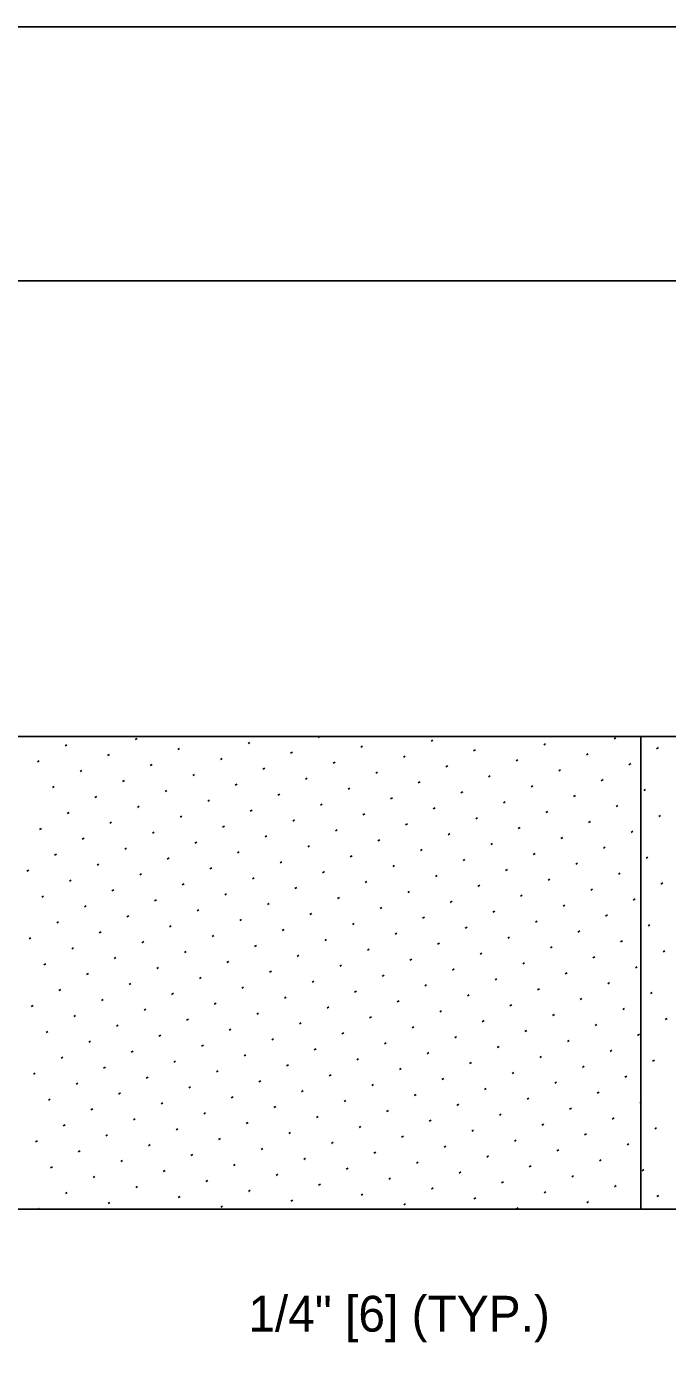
# Model space of a CAD drawing. Extents: x 49991.4 to 50021, y 49987.6 to 50011.4.
# Drawn here: x 50003.6 to 50004.674, y 49996.76 to 49998.999 of the extents above; entities that cross this region are included whole.
import ezdxf

# ---------------------------------------------------------------- set-up
doc = ezdxf.new("R2010")
doc.units = 0
for name, color, linetype in [('Level 1', 7, 'Continuous'), ('Level 2', 7, 'Continuous'), ('Level 3', 7, 'Continuous'), ('Level 6', 7, 'Continuous')]:
    doc.layers.add(name, color=color, linetype=linetype)

msp = doc.modelspace()

# ---------------------------------------------------------------- linework, layer by layer
at = {"layer": 'Level 1'}
for p, q in [((50002.4589, 49997.8102), (50013.6129, 49997.8102)), ((50013.6129, 49997.0183), (50002.4589, 49997.0183))]:
    msp.add_line(p, q, dxfattribs=at)
msp.add_lwpolyline([(49999.3835, 49998.9992), (50016.7501, 49998.9992), (50016.7501, 49987.7988), (49999.3835, 49987.7988)], close=True, dxfattribs=at)
at = {"layer": 'Level 3'}
for p, q in [((50003.6644, 49997.7948), (50003.6674, 49997.7965)), ((50003.7821, 49997.805), (50003.7851, 49997.8067)), ((50003.9711, 49997.7986), (50003.9741, 49997.8004)), ((50004.0887, 49997.8088), (50004.0911, 49997.8102)), ((50004.1601, 49997.7923), (50004.1631, 49997.794)), ((50004.2778, 49997.8025), (50004.2808, 49997.8043)), ((50004.4668, 49997.7962), (50004.4698, 49997.7979)), ((50004.5845, 49997.8064), (50004.5875, 49997.8081)), ((50004.6295, 49997.0183), (50004.6295, 49997.8102)), ((50003.7357, 49997.7782), (50003.7387, 49997.78)), ((50003.8534, 49997.7884), (50003.8564, 49997.7902)), ((50003.9247, 49997.7719), (50003.9278, 49997.7736)), ((50004.0424, 49997.7821), (50004.0454, 49997.7838)), ((50004.2314, 49997.7757), (50004.2345, 49997.7775)), ((50004.3491, 49997.786), (50004.3521, 49997.7877)), ((50004.4204, 49997.7694), (50004.4235, 49997.7712)), ((50004.5381, 49997.7796), (50004.5411, 49997.7814)), ((50004.6558, 49997.7898), (50004.6588, 49997.7916)), ((50003.618, 49997.768), (50003.6211, 49997.7698)), ((50003.6894, 49997.7515), (50003.6924, 49997.7532)), ((50003.8071, 49997.7617), (50003.8101, 49997.7634)), ((50003.9961, 49997.7553), (50003.9991, 49997.7571)), ((50004.1137, 49997.7655), (50004.1168, 49997.7673)), ((50004.1851, 49997.749), (50004.1881, 49997.7507)), ((50004.3028, 49997.7592), (50004.3058, 49997.761)), ((50004.4918, 49997.7529), (50004.4948, 49997.7546)), ((50004.6095, 49997.7631), (50004.6125, 49997.7648)), ((50003.643, 49997.7247), (50003.6461, 49997.7265)), ((50003.7607, 49997.7349), (50003.7637, 49997.7367)), ((50003.8784, 49997.7451), (50003.8814, 49997.7469)), ((50003.9497, 49997.7286), (50003.9528, 49997.7303)), ((50004.0674, 49997.7388), (50004.0704, 49997.7405)), ((50004.2564, 49997.7324), (50004.2595, 49997.7342)), ((50004.3741, 49997.7427), (50004.3771, 49997.7444)), ((50004.4454, 49997.7261), (50004.4485, 49997.7279)), ((50004.5631, 49997.7363), (50004.5661, 49997.7381)), ((50003.7144, 49997.7082), (50003.7174, 49997.7099)), ((50003.8321, 49997.7184), (50003.8351, 49997.7201)), ((50003.9034, 49997.7018), (50003.9064, 49997.7036)), ((50004.0211, 49997.712), (50004.0241, 49997.7138)), ((50004.1387, 49997.7222), (50004.1418, 49997.724)), ((50004.2101, 49997.7057), (50004.2131, 49997.7074)), ((50004.3278, 49997.7159), (50004.3308, 49997.7176)), ((50004.5168, 49997.7096), (50004.5198, 49997.7113)), ((50004.6345, 49997.7198), (50004.6375, 49997.7215)), ((50003.668, 49997.6814), (50003.6711, 49997.6832)), ((50003.7857, 49997.6916), (50003.7887, 49997.6934)), ((50003.9747, 49997.6853), (50003.9778, 49997.687)), ((50004.0924, 49997.6955), (50004.0954, 49997.6972)), ((50004.1637, 49997.6789), (50004.1668, 49997.6807)), ((50004.2814, 49997.6891), (50004.2845, 49997.6909)), ((50004.3991, 49997.6994), (50004.4021, 49997.7011)), ((50004.4704, 49997.6828), (50004.4735, 49997.6846)), ((50004.5881, 49997.693), (50004.5911, 49997.6948)), ((50003.7394, 49997.6649), (50003.7424, 49997.6666)), ((50003.8571, 49997.6751), (50003.8601, 49997.6768)), ((50003.9284, 49997.6585), (50003.9314, 49997.6603)), ((50004.0461, 49997.6687), (50004.0491, 49997.6705)), ((50004.2351, 49997.6624), (50004.2381, 49997.6641)), ((50004.3528, 49997.6726), (50004.3558, 49997.6743)), ((50004.5418, 49997.6663), (50004.5448, 49997.668)), ((50004.6595, 49997.6765), (50004.6625, 49997.6782)), ((50003.6217, 49997.6547), (50003.6247, 49997.6564)), ((50003.693, 49997.6381), (50003.6961, 49997.6399)), ((50003.8107, 49997.6483), (50003.8137, 49997.6501)), ((50003.9997, 49997.642), (50004.0028, 49997.6437)), ((50004.1174, 49997.6522), (50004.1204, 49997.6539)), ((50004.1887, 49997.6356), (50004.1918, 49997.6374)), ((50004.3064, 49997.6458), (50004.3095, 49997.6476)), ((50004.4241, 49997.656), (50004.4271, 49997.6578)), ((50004.4954, 49997.6395), (50004.4985, 49997.6413)), ((50004.6131, 49997.6497), (50004.6161, 49997.6515)), ((50003.7644, 49997.6216), (50003.7674, 49997.6233)), ((50003.8821, 49997.6318), (50003.8851, 49997.6335)), ((50003.9534, 49997.6152), (50003.9564, 49997.617)), ((50004.0711, 49997.6254), (50004.0741, 49997.6272)), ((50004.2601, 49997.6191), (50004.2631, 49997.6208)), ((50004.3778, 49997.6293), (50004.3808, 49997.631)), ((50004.4491, 49997.6127), (50004.4521, 49997.6145)), ((50004.5668, 49997.623), (50004.5698, 49997.6247)), ((50003.6467, 49997.6114), (50003.6497, 49997.6131)), ((50003.718, 49997.5948), (50003.7211, 49997.5966)), ((50003.8357, 49997.605), (50003.8387, 49997.6068)), ((50004.0247, 49997.5987), (50004.0278, 49997.6004)), ((50004.1424, 49997.6089), (50004.1454, 49997.6106)), ((50004.2137, 49997.5923), (50004.2168, 49997.5941)), ((50004.3314, 49997.6025), (50004.3345, 49997.6043)), ((50004.5204, 49997.5962), (50004.5235, 49997.598)), ((50004.6381, 49997.6064), (50004.6411, 49997.6082)), ((50003.6004, 49997.5846), (50003.6034, 49997.5864)), ((50003.6717, 49997.5681), (50003.6747, 49997.5698)), ((50003.7894, 49997.5783), (50003.7924, 49997.58)), ((50003.9071, 49997.5885), (50003.9101, 49997.5902)), ((50003.9784, 49997.5719), (50003.9814, 49997.5737)), ((50004.0961, 49997.5821), (50004.0991, 49997.5839)), ((50004.2851, 49997.5758), (50004.2881, 49997.5775)), ((50004.4028, 49997.586), (50004.4058, 49997.5877)), ((50004.4741, 49997.5694), (50004.4771, 49997.5712)), ((50004.5918, 49997.5797), (50004.5948, 49997.5814)), ((50003.743, 49997.5515), (50003.7461, 49997.5533)), ((50003.8607, 49997.5617), (50003.8637, 49997.5635)), ((50003.9321, 49997.5452), (50003.9351, 49997.5469)), ((50004.0497, 49997.5554), (50004.0528, 49997.5571)), ((50004.1674, 49997.5656), (50004.1704, 49997.5673)), ((50004.2387, 49997.549), (50004.2418, 49997.5508)), ((50004.3564, 49997.5592), (50004.3595, 49997.561)), ((50004.5454, 49997.5529), (50004.5485, 49997.5546)), ((50004.6631, 49997.5631), (50004.6661, 49997.5649)), ((50003.6254, 49997.5413), (50003.6284, 49997.5431)), ((50003.6967, 49997.5248), (50003.6997, 49997.5265)), ((50003.8144, 49997.535), (50003.8174, 49997.5367)), ((50004.0034, 49997.5286), (50004.0064, 49997.5304)), ((50004.1211, 49997.5388), (50004.1241, 49997.5406)), ((50004.1924, 49997.5223), (50004.1954, 49997.524)), ((50004.3101, 49997.5325), (50004.3131, 49997.5342)), ((50004.4278, 49997.5427), (50004.4308, 49997.5444)), ((50004.4991, 49997.5261), (50004.5021, 49997.5279)), ((50004.6168, 49997.5364), (50004.6198, 49997.5381)), ((50003.768, 49997.5082), (50003.7711, 49997.51)), ((50003.8857, 49997.5184), (50003.8887, 49997.5202)), ((50003.9571, 49997.5019), (50003.9601, 49997.5036)), ((50004.0747, 49997.5121), (50004.0778, 49997.5138)), ((50004.2637, 49997.5057), (50004.2668, 49997.5075)), ((50004.3814, 49997.5159), (50004.3845, 49997.5177)), ((50004.5704, 49997.5096), (50004.5735, 49997.5113)), ((50003.6504, 49997.498), (50003.6534, 49997.4998)), ((50003.7217, 49997.4815), (50003.7247, 49997.4832)), ((50003.8394, 49997.4917), (50003.8424, 49997.4934)), ((50004.0284, 49997.4853), (50004.0314, 49997.4871)), ((50004.1461, 49997.4955), (50004.1491, 49997.4973)), ((50004.2174, 49997.479), (50004.2204, 49997.4807)), ((50004.3351, 49997.4892), (50004.3381, 49997.4909)), ((50004.4528, 49997.4994), (50004.4558, 49997.5011)), ((50004.5241, 49997.4828), (50004.5271, 49997.4846)), ((50004.6418, 49997.4931), (50004.6448, 49997.4948)), ((50003.604, 49997.4713), (50003.6071, 49997.473)), ((50003.793, 49997.4649), (50003.7961, 49997.4667)), ((50003.9107, 49997.4751), (50003.9137, 49997.4769)), ((50003.9821, 49997.4586), (50003.9851, 49997.4603)), ((50004.0997, 49997.4688), (50004.1028, 49997.4705)), ((50004.2887, 49997.4624), (50004.2918, 49997.4642)), ((50004.4064, 49997.4726), (50004.4095, 49997.4744)), ((50004.4778, 49997.4561), (50004.4808, 49997.4578)), ((50004.5954, 49997.4663), (50004.5985, 49997.468)), ((50003.6754, 49997.4547), (50003.6784, 49997.4565)), ((50003.7467, 49997.4382), (50003.7497, 49997.4399)), ((50003.8644, 49997.4484), (50003.8674, 49997.4501)), ((50004.0534, 49997.442), (50004.0564, 49997.4438)), ((50004.1711, 49997.4522), (50004.1741, 49997.454)), ((50004.2424, 49997.4357), (50004.2454, 49997.4374)), ((50004.3601, 49997.4459), (50004.3631, 49997.4476)), ((50004.5491, 49997.4395), (50004.5521, 49997.4413)), ((50004.6668, 49997.4497), (50004.6698, 49997.4515)), ((50003.629, 49997.428), (50003.6321, 49997.4297)), ((50003.7004, 49997.4114), (50003.7034, 49997.4132)), ((50003.818, 49997.4216), (50003.8211, 49997.4234)), ((50003.9357, 49997.4318), (50003.9387, 49997.4336)), ((50004.0071, 49997.4153), (50004.0101, 49997.417)), ((50004.1247, 49997.4255), (50004.1278, 49997.4272)), ((50004.3137, 49997.4191), (50004.3168, 49997.4209)), ((50004.4314, 49997.4293), (50004.4345, 49997.4311)), ((50004.5028, 49997.4128), (50004.5058, 49997.4145)), ((50004.6204, 49997.423), (50004.6235, 49997.4247)), ((50003.7717, 49997.3949), (50003.7747, 49997.3966)), ((50003.8894, 49997.4051), (50003.8924, 49997.4068)), ((50003.9607, 49997.3885), (50003.9637, 49997.3903)), ((50004.0784, 49997.3987), (50004.0814, 49997.4005)), ((50004.1961, 49997.4089), (50004.1991, 49997.4107)), ((50004.2674, 49997.3924), (50004.2704, 49997.3941)), ((50004.3851, 49997.4026), (50004.3881, 49997.4043)), ((50004.5741, 49997.3962), (50004.5771, 49997.398)), ((50003.654, 49997.3847), (50003.6571, 49997.3864)), ((50003.7254, 49997.3681), (50003.7284, 49997.3699)), ((50003.843, 49997.3783), (50003.8461, 49997.3801)), ((50004.0321, 49997.372), (50004.0351, 49997.3737)), ((50004.1497, 49997.3822), (50004.1528, 49997.3839)), ((50004.2211, 49997.3656), (50004.2241, 49997.3674)), ((50004.3387, 49997.3758), (50004.3418, 49997.3776)), ((50004.4564, 49997.386), (50004.4595, 49997.3878)), ((50004.5278, 49997.3695), (50004.5308, 49997.3712)), ((50004.6454, 49997.3797), (50004.6485, 49997.3814)), ((50003.6077, 49997.3579), (50003.6107, 49997.3596)), ((50003.7967, 49997.3516), (50003.7997, 49997.3533)), ((50003.9144, 49997.3618), (50003.9174, 49997.3635)), ((50003.9857, 49997.3452), (50003.9887, 49997.347)), ((50004.1034, 49997.3554), (50004.1064, 49997.3572)), ((50004.2924, 49997.3491), (50004.2954, 49997.3508)), ((50004.4101, 49997.3593), (50004.4131, 49997.361)), ((50004.5991, 49997.3529), (50004.6021, 49997.3547)), ((50003.679, 49997.3414), (50003.6821, 49997.3431)), ((50003.7504, 49997.3248), (50003.7534, 49997.3266)), ((50003.868, 49997.335), (50003.8711, 49997.3368)), ((50004.0571, 49997.3287), (50004.0601, 49997.3304)), ((50004.1747, 49997.3389), (50004.1778, 49997.3406)), ((50004.2461, 49997.3223), (50004.2491, 49997.3241)), ((50004.3637, 49997.3325), (50004.3668, 49997.3343)), ((50004.4814, 49997.3427), (50004.4845, 49997.3445)), ((50004.5528, 49997.3262), (50004.5558, 49997.3279)), ((50004.6704, 49997.3364), (50004.6735, 49997.3381)), ((50003.6327, 49997.3146), (50003.6357, 49997.3163)), ((50003.8217, 49997.3083), (50003.8247, 49997.31)), ((50003.9394, 49997.3185), (50003.9424, 49997.3202)), ((50004.0107, 49997.3019), (50004.0137, 49997.3037)), ((50004.1284, 49997.3121), (50004.1314, 49997.3139)), ((50004.3174, 49997.3058), (50004.3204, 49997.3075)), ((50004.4351, 49997.316), (50004.4381, 49997.3177)), ((50004.5064, 49997.2994), (50004.5095, 49997.3012)), ((50004.6241, 49997.3096), (50004.6271, 49997.3114)), ((50003.704, 49997.298), (50003.7071, 49997.2998)), ((50003.7754, 49997.2815), (50003.7784, 49997.2833)), ((50003.893, 49997.2917), (50003.8961, 49997.2935)), ((50004.0821, 49997.2854), (50004.0851, 49997.2871)), ((50004.1997, 49997.2956), (50004.2028, 49997.2973)), ((50004.2711, 49997.279), (50004.2741, 49997.2808)), ((50004.3887, 49997.2892), (50004.3918, 49997.291)), ((50004.5778, 49997.2829), (50004.5808, 49997.2846)), ((50003.6577, 49997.2713), (50003.6607, 49997.273)), ((50003.729, 49997.2547), (50003.7321, 49997.2565)), ((50003.8467, 49997.265), (50003.8497, 49997.2667)), ((50003.9644, 49997.2752), (50003.9674, 49997.2769)), ((50004.0357, 49997.2586), (50004.0387, 49997.2604)), ((50004.1534, 49997.2688), (50004.1564, 49997.2706)), ((50004.3424, 49997.2625), (50004.3454, 49997.2642)), ((50004.4601, 49997.2727), (50004.4631, 49997.2744)), ((50004.5314, 49997.2561), (50004.5345, 49997.2579)), ((50004.6491, 49997.2663), (50004.6521, 49997.2681)), ((50003.6113, 49997.2445), (50003.6144, 49997.2463)), ((50003.8004, 49997.2382), (50003.8034, 49997.2399)), ((50003.918, 49997.2484), (50003.9211, 49997.2502)), ((50003.9894, 49997.2319), (50003.9924, 49997.2336)), ((50004.1071, 49997.2421), (50004.1101, 49997.2438)), ((50004.2247, 49997.2523), (50004.2278, 49997.254)), ((50004.2961, 49997.2357), (50004.2991, 49997.2375)), ((50004.4137, 49997.2459), (50004.4168, 49997.2477)), ((50004.6028, 49997.2396), (50004.6058, 49997.2413)), ((50003.6827, 49997.228), (50003.6857, 49997.2297)), ((50003.754, 49997.2114), (50003.7571, 49997.2132)), ((50003.8717, 49997.2217), (50003.8747, 49997.2234)), ((50004.0607, 49997.2153), (50004.0637, 49997.2171)), ((50004.1784, 49997.2255), (50004.1814, 49997.2273)), ((50004.2497, 49997.209), (50004.2528, 49997.2107)), ((50004.3674, 49997.2192), (50004.3704, 49997.2209)), ((50004.4851, 49997.2294), (50004.4881, 49997.2311)), ((50004.5564, 49997.2128), (50004.5595, 49997.2146)), ((50003.6363, 49997.2012), (50003.6394, 49997.203)), ((50003.8254, 49997.1949), (50003.8284, 49997.1966)), ((50003.943, 49997.2051), (50003.9461, 49997.2069)), ((50004.0144, 49997.1886), (50004.0174, 49997.1903)), ((50004.1321, 49997.1988), (50004.1351, 49997.2005)), ((50004.3211, 49997.1924), (50004.3241, 49997.1942)), ((50004.4387, 49997.2026), (50004.4418, 49997.2044)), ((50004.6278, 49997.1963), (50004.6308, 49997.198)), ((50003.7077, 49997.1847), (50003.7107, 49997.1864)), ((50003.779, 49997.1681), (50003.7821, 49997.1699)), ((50003.8967, 49997.1784), (50003.8997, 49997.1801)), ((50004.0857, 49997.172), (50004.0887, 49997.1738)), ((50004.2034, 49997.1822), (50004.2064, 49997.184)), ((50004.2747, 49997.1657), (50004.2778, 49997.1674)), ((50004.3924, 49997.1759), (50004.3954, 49997.1776)), ((50004.5101, 49997.1861), (50004.5131, 49997.1878)), ((50004.5814, 49997.1695), (50004.5845, 49997.1713)), ((50003.6613, 49997.1579), (50003.6644, 49997.1597)), ((50003.8504, 49997.1516), (50003.8534, 49997.1533)), ((50003.968, 49997.1618), (50003.9711, 49997.1636)), ((50004.0394, 49997.1453), (50004.0424, 49997.147)), ((50004.1571, 49997.1555), (50004.1601, 49997.1572)), ((50004.3461, 49997.1491), (50004.3491, 49997.1509)), ((50004.4637, 49997.1593), (50004.4668, 49997.1611)), ((50004.5351, 49997.1428), (50004.5381, 49997.1445)), ((50004.6528, 49997.153), (50004.6558, 49997.1547)), ((50003.615, 49997.1312), (50003.618, 49997.1329)), ((50003.7327, 49997.1414), (50003.7357, 49997.1431)), ((50003.804, 49997.1248), (50003.8071, 49997.1266)), ((50003.9217, 49997.135), (50003.9247, 49997.1368)), ((50004.1107, 49997.1287), (50004.1137, 49997.1305)), ((50004.2284, 49997.1389), (50004.2314, 49997.1407)), ((50004.2997, 49997.1224), (50004.3028, 49997.1241)), ((50004.4174, 49997.1326), (50004.4204, 49997.1343)), ((50004.6064, 49997.1262), (50004.6095, 49997.128)), ((50003.6863, 49997.1146), (50003.6894, 49997.1164)), ((50003.7577, 49997.0981), (50003.7607, 49997.0998)), ((50003.8754, 49997.1083), (50003.8784, 49997.11)), ((50003.993, 49997.1185), (50003.9961, 49997.1203)), ((50004.0644, 49997.102), (50004.0674, 49997.1037)), ((50004.1821, 49997.1122), (50004.1851, 49997.1139)), ((50004.3711, 49997.1058), (50004.3741, 49997.1076)), ((50004.4887, 49997.116), (50004.4918, 49997.1178)), ((50004.5601, 49997.0995), (50004.5631, 49997.1012)), ((50003.64, 49997.0879), (50003.643, 49997.0896)), ((50003.829, 49997.0815), (50003.8321, 49997.0833)), ((50003.9467, 49997.0917), (50003.9497, 49997.0935)), ((50004.018, 49997.0752), (50004.0211, 49997.077)), ((50004.1357, 49997.0854), (50004.1387, 49997.0872)), ((50004.2534, 49997.0956), (50004.2564, 49997.0974)), ((50004.3247, 49997.0791), (50004.3278, 49997.0808)), ((50004.4424, 49997.0893), (50004.4454, 49997.091)), ((50004.6314, 49997.0829), (50004.6345, 49997.0847)), ((50003.7113, 49997.0713), (50003.7144, 49997.0731)), ((50003.7827, 49997.0548), (50003.7857, 49997.0565)), ((50003.9004, 49997.065), (50003.9034, 49997.0667)), ((50004.0894, 49997.0587), (50004.0924, 49997.0604)), ((50004.2071, 49997.0689), (50004.2101, 49997.0706)), ((50004.2784, 49997.0523), (50004.2814, 49997.0541)), ((50004.3961, 49997.0625), (50004.3991, 49997.0643)), ((50004.5137, 49997.0727), (50004.5168, 49997.0745)), ((50004.5851, 49997.0562), (50004.5881, 49997.0579)), ((50003.665, 49997.0446), (50003.668, 49997.0463)), ((50003.854, 49997.0382), (50003.8571, 49997.04)), ((50003.9717, 49997.0484), (50003.9747, 49997.0502)), ((50004.043, 49997.0319), (50004.0461, 49997.0336)), ((50004.1607, 49997.0421), (50004.1637, 49997.0439)), ((50004.3497, 49997.0358), (50004.3528, 49997.0375)), ((50004.4674, 49997.046), (50004.4704, 49997.0477)), ((50004.6564, 49997.0396), (50004.6595, 49997.0414)), ((50003.6194, 49997.0183), (50003.6217, 49997.0196)), ((50003.7363, 49997.028), (50003.7394, 49997.0298)), ((50003.9254, 49997.0217), (50003.9284, 49997.0234)), ((50004.2321, 49997.0256), (50004.2351, 49997.0273)), ((50004.4211, 49997.0192), (50004.4241, 49997.021)), ((50004.5387, 49997.0294), (50004.5418, 49997.0312))]:
    msp.add_line(p, q, dxfattribs=at)
at = {"layer": 'Level 6'}
msp.add_line((50004.8695, 49998.5733), (50001.9365, 49998.5733), dxfattribs=at)

# ---------------------------------------------------------------- texts
at = {"layer": 'Level 2'}
msp.add_text(' 1/4" [6] (TYP.)', height=0.06, dxfattribs=at).set_placement((50003.9491, 49996.8134))

doc.saveas('drawing.dxf')
